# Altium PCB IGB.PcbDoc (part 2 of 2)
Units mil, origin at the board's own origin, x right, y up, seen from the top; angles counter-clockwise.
Board outline 7000 x 12000 mil, 4 copper layers (Top Layer, GND, PWR, Bottom Layer), stack 55.52 mil thick; 229 components, 204 nets, 726 pads, 127 vias.
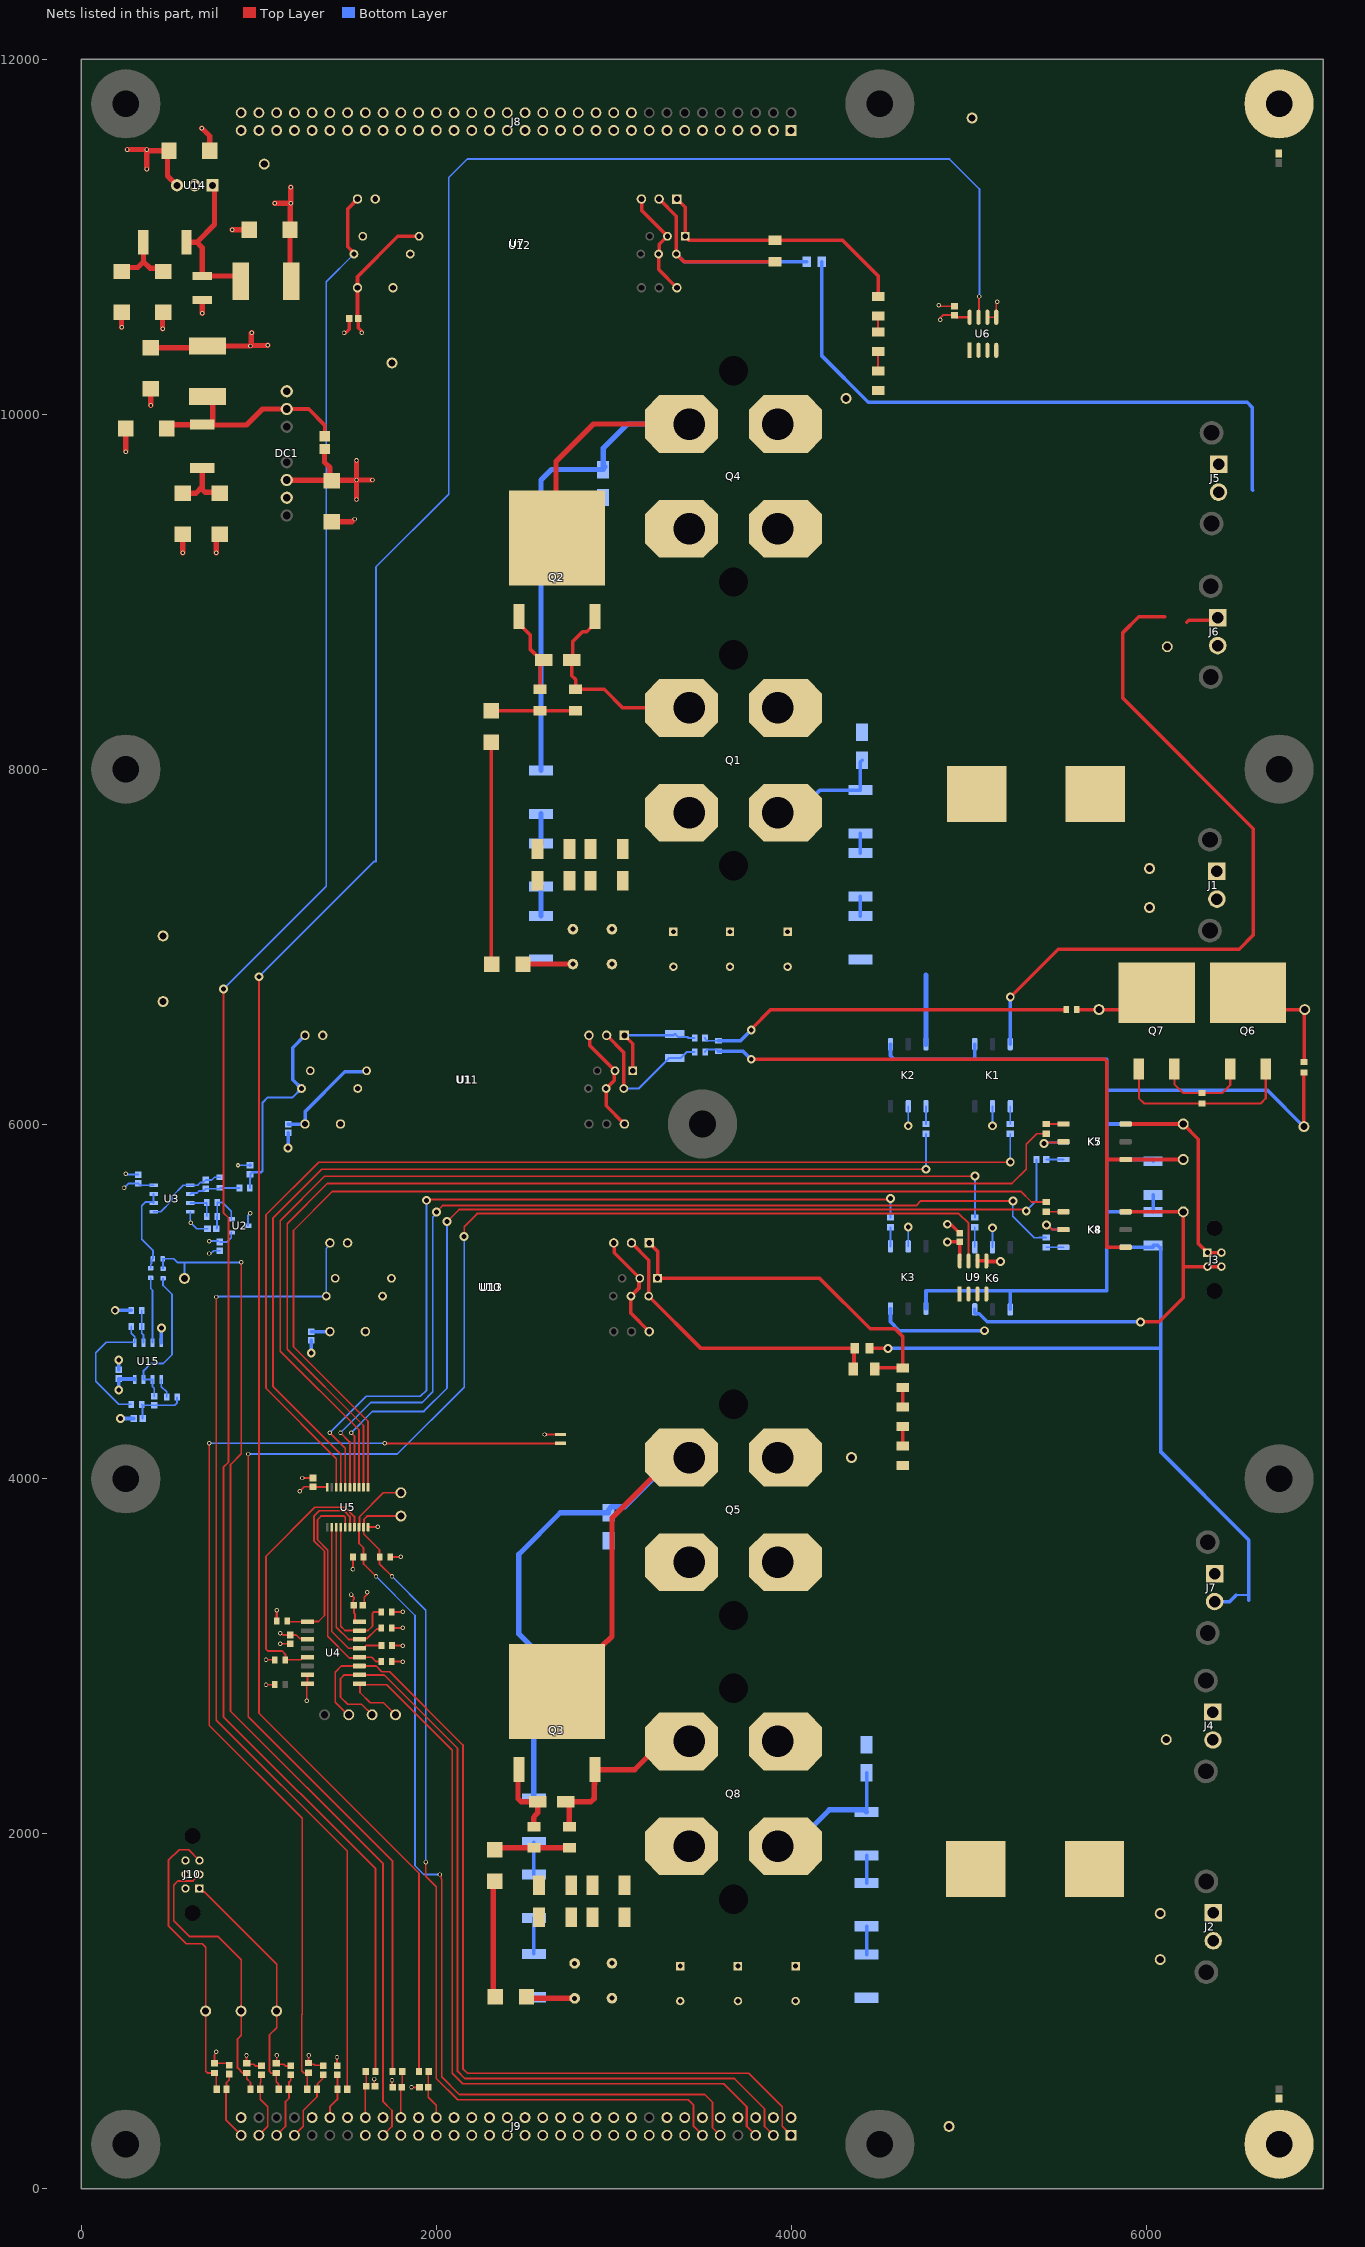
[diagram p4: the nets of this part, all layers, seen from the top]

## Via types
v1: diameter 25, hole 15, Top Layer to Bottom Layer, 92 vias
v2: diameter 50, hole 28, Top Layer to Bottom Layer, 34 vias
v3: diameter 25, hole 10, Top Layer to Bottom Layer, 1 vias

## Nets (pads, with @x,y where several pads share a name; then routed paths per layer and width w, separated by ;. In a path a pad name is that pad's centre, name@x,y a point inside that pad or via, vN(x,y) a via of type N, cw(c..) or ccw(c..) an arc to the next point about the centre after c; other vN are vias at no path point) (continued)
GND: C1.2 C2.2 C4.2 C12.1 C13.1 C14.1 C16.1 C17.1 C18.1 C19.1 C20.1 C21.1 C22.1 C23.1 C24.1 C25.1 C26.1 C27.1 C28.1 C29.1 C30.1 C31.2 C32.1 C33.2 C38.2 C39.2 C40.2 C41.2 C42.1 C43.1 C44.1 C46.1 DC1.1 DC1.7 J8.20 J8.24 J8.28 J8.32 J8.54 J8.55 J8.57 J8.59 J8.61 J8.63 J9.4 J9.8 J9.12 J9.13 J9.16 J9.17 J9.20 J9.21 J9.24 J9.25 J9.28 J9.29 J9.32 J9.33 J9.37 J9.40 J9.41 J9.44 J9.45 J9.48 J9.49 J9.52 J9.56 J36.1 J37.1 J38.1 K1.2 K2.2 K3.2 K4.2 K5.2 K6.2 K7.2 K8.2 R22.1 R23.1 R24.1 R25.1 R26.1 R27.1 R28.1 R29.1 R43.1 R45.1 R48.1 R50.1 R77.1 U1.18 U1.22 U2.3 U3.4 U4.7 U4.8 U5.10 U6.5 U6.6 U7.18 U7.22 U9.5 U9.6 U10.18 U10.22 U11.32 U11.37 U12.32 U12.37 U13.32 U13.37 U14.2 U15.4 | length 4984.8
  Top Layer w10: v1(760,770) 760,764.59 750,754.59 R45.1@750,705.84 821.61,705.84 C23.1@832.84,694.61 ; v1(930,750) 930,707.3 R48.1@931.47,705.84 937.3,700 970,700 978.93,691.07 C24.1@1014.31,691.07 ; v1(1040,2980) R27.1@1090.47,2980 ; v1(1100,750) 1100,708.68 R43.1@1097.16,705.84 1102.99,700 1140,700 1148.93,691.07 C22.1@1180,691.07 ; v1(1120,3070) 1174.84,3070 C17.1@1175.74,3070.9 ; v1@1240,4000 v1(1244.61,4004.61) C18.1@1304.95,4004.61 ; v1(1270,2750) 1270,2842.2 1272.8,2845 U4.8@1273.35,2845 U4.7@1273.35,2895 ; v1(1280,750) 1280,717.56 1270,707.56 1277.56,700 1310,700 1315.39,694.61 C26.1@1352.84,694.61 ; C30.1@1440,691.07 v1(1440,740) ; v1(1530,3490) 1530.47,3490.47 R28.1@1530.47,3560 ; C42.1@1584.61,3287.88 1593.31,3296.59 1593.31,3333.31 v1@1610,3350 ; U5.10@1615.16,3727.8 1667.8,3727.8 v1(1670,3730) ; v1(1650,616.83) 1650,581.76 C25.1@1654.61,577.16 ; R29.1@1739.53,3560 v1@1790,3560 ; R25.1@1749.06,2969.28 1749.77,2970 v1(1810,2970) ; R23.1@1749.53,3159.28 1750.25,3160 v1(1810,3160) ; R24.1@1749.53,3250 v1(1810,3250) ; v1(1750,610) 1750,575.39 C29.1@1755.39,570 ; R22.1@1750,3060 v1(1810,3060) ; v1(1860,570) C21.1@1905.39,570 ; v1(4831,10614) 4836.39,10608.61 C19.1@4921,10608.61 ; U9.5@5100,5228.06 U9.5@5103.06,5225 ; U6.6@5106,10547.06 U6.5@5156,10547.06 5156,10629 v1(5161,10634) ; v2(5425,5890) 5430,5895 5529.8,5895 K7.2@5534.8,5900 ; v2(5440,5430) 5446.57,5430 5471.57,5405 K8.2@5534.8,5405
  Top Layer w12: v1@1100,3250 1100.47,3249.53 R26.1@1100.47,3200
  Top Layer w20: v1@1490,10460 1510,10480 C20.1@1510,10540 ; v2(4880,5435) 4885.74,5429.26 4905.35,5429.26 C27.1@4950,5384.61 ; U9.6@5050,5228.06 U9.5@5100,5228.06 ; U9.5@5103.06,5225 v2(5180,5225)
  Top Layer w30: v1(226.02,10490) C40.2@226.02,10574.84 ; C2.2@249.68,9920 249.68,9790.32 v1(250,9790) ; v1(390,10050) C1.2@390,10144.84 ; v1(457.12,10482.81) 457.12,10571.96 C41.2@460,10574.84 ; v1(570,9220) C38.2@570,9324.84 ; v1(678.16,11612.39) 723.32,11567.23 C33.2@723.32,11485 ; v1(680,10570) C32.1@680,10644.17 ; v1(760,9220) 760,9304.84 C39.2@780,9324.84 ; v1(850,11040) C31.2@944.84,11040 ; C4.2@1410,9394.84 1524.84,9394.84 1530,9400
  Bottom Layer w10: v1(250,5720) 255.39,5714.61 C13.1@320,5714.61 ; v1@613.35,5446.65 U3.4@613.35,5505 ; v1(616.67,5443.33) 650,5410 C14.1@710.39,5410 ; v1(720,5270) 729.19,5270 744.58,5285.39 C16.1@780,5285.39 ; v3@882.7,5767.3 C46.1@949.3,5767.3 ; U2.3@939.24,5426 939.24,5485.24 v1(950.62,5496.62) ; K3.2@4660,5310.2 v2(4660,5420) ; v2(4660,5990) K2.2@4660,6099.8 ; K6.2@5135,5305.2 v2(5135,5415) ; v2(5135,5990) K1.2@5135,6099.8 ; v2(5425,5890) 5430,5895 5529.61,5895 K5.2@5534.61,5900 ; v2(5440,5430) 5446.57,5430 5471.57,5405 K4.2@5534.61,5405
  Bottom Layer w20: v2(190,4950) R77.1@280.47,4950 ; C43.1@210,4614.61 v2(210,4670) ; v2(220,4340) C44.1@295.39,4340 ; U15.4@450,4766.69 v2(450,4850) ; v3(882,5768) v3@882.7,5767.3 ; C46.1@949.3,5767.3 C46.1@950,5766.61 ; v2(1165,5865) C12.1@1165,5950.39 ; v2(1295,4710) C28.1@1295,4780.79
  other v1: 1100,3260 1610,3360 1800,3560 1540,9410 1480,10460
HCB_MEDIA_EN: J8.30
HPB_5V_CURRENT: J9.34
HPB_5V_VOLTAGE: J9.30
HPB_24V_CURRENT: J9.26
HPB_24V_VOLTAGE: J9.22
HPB_CISCO1_CURRENT: J9.2
HPB_CISCO1_EN: J8.49
HPB_CISCO2_CURRENT: J9.6
HPB_CISCO2_EN: J8.51
HPB_ISO24V_CURRENT: J9.14
HPB_MEDIA_CURRENT: J9.64
HPB_SYNCBOX_CURRENT: J9.10
HPB_SYNCBOX_EN: J8.53
HPB_TEMP0: J8.44
HPB_TEMP1: J8.46
HPB_TEMP2: J8.48
HPB_TEMP3: J8.50
HPB_TEMP4: J8.52
HPB_VICOR1_TEMP: J8.38
HPB_VICOR2_TEMP: J8.40
HPB_VICOR3_TEMP: J8.42
I2C_SCL: J8.26
I2C_SDA: J8.22
IGB1_CHB_RLY_EN: J8.25
INPUT+: C11.2 R17.2 U1.1 U11.1 | length 627.7
  Top Layer w20: U1.1@3060,6500 3107,6453 U11.1@3107,6300
  Bottom Layer w12: U1.1@3060,6500 3337.09,6500 C11.2@3345,6507.91 3361.64,6491.28 3415.45,6491.28 3421.72,6485 R17.2@3455.47,6485
INPUT-: U1.3 U1.38 U11.3 U11.4 | length 624.3
  Top Layer w20: U1.3@2860,6500 2863.57,6496.43 2863.57,6443.43 U11.3@3007,6300 3002.39,6295.39 3002.39,6245.39 U11.4@2957,6200 2957,6103 U1.38@3060,6000
INPUT_COMMON: C11.1 R18.2 U1.2 U11.2 | length 824
  Top Layer w20: U1.2@2960,6500 3057,6403 U11.2@3057,6200
  Bottom Layer w12: U11.2@3057,6200 3140.43,6200 3312.52,6372.09 C11.1@3345,6372.09 3377.48,6372.09 3410.39,6405 R18.2@3455.94,6405
IPB1_BOARD_TEMP: J8.34
IPB1_CHA_CURRENT_SET: J8.1
IPB1_CHA_FET_EN: J8.21
IPB1_CHA_I: J9.15
IPB1_CHA_RLY_EN: J8.17
IPB1_CHB_CURRENT_SET: J8.5
IPB1_CHB_FET_EN: J8.29
IPB1_CHB_I: J9.23
IPB1_CHC_CURRENT_SET: J8.9
IPB1_CHC_FET_EN: J8.37
IPB1_CHC_I: J9.31
IPB1_CHC_RLY_EN: J8.33
IPB1_CHD_CURRENT_SET: J8.13
IPB1_CHD_FET_EN: J8.45
IPB1_CHD_I: J9.39
IPB1_CHD_RLY_EN: J8.41
IPB1_RESET: J9.36
IPB2_BOARD_TEMP: J8.36
IPB2_CHA_CURRENT_SET: J8.3
IPB2_CHA_FET_EN: J8.23
IPB2_CHA_I: J9.19
IPB2_CHA_RLY_EN: J8.19
IPB2_CHB_CURRENT_SET: J8.7
IPB2_CHB_FET_EN: J8.31
IPB2_CHB_I: J9.27
IPB2_CHB_RLY_EN: J8.27
IPB2_CHC_CURRENT_SET: J8.11
IPB2_CHC_FET_EN: J8.39
IPB2_CHC_I: J9.35
IPB2_CHC_RLY_EN: J8.35
IPB2_CHD_CURRENT_SET: J8.15
IPB2_CHD_FET_EN: J8.47
IPB2_CHD_I: J9.43
IPB2_CHD_RLY_EN: J8.43
IPB2_RESET: J9.38
L_INPUT+: R52.2 R66.2 U10.1 U13.1 | length 2076.1
  Top Layer w20: U10.1@3200,5330 3247,5283 U13.1@3247,5130 4160,5130 4445,4845 4585,4845 4630,4800 R66.2@4630,4625.12 4475.16,4625.12 R52.2@4470.04,4620
L_INPUT-: U10.3 U10.38 U13.3 U13.4 | length 624.3
  Top Layer w20: U10.3@3000,5330 3003.57,5326.43 3003.57,5273.43 U13.3@3147,5130 3142.39,5125.39 3142.39,5075.39 U13.4@3097,5030 3097,4933 U10.38@3200,4830
L_INPUT_COMMON: R14.2 R52.1 U10.2 U13.2 | length 1742.6
  Top Layer w20: U10.2@3100,5330 3197,5233 U13.2@3197,5030 3492,4735 R14.2@4358.66,4735 4354.31,4730.65 4354.31,4624.35 R52.1@4349.96,4620
L_OUTPUT_HIGH: R54.1 U10.19 U13.38 | length 5700.9
  Top Layer w10: v1(760,5025) 760,2640 1497.56,1902.44 R54.1@1497.56,560
  Bottom Layer w10: v1(760,5025) 762.5,5027.5 1377.5,5027.5 U13.38@1380,5030 1380,5298.32 1400,5318.32 U10.19@1400,5330
N187_L_OUT: C6.2 C8.2 C10.2 C35.1 C37.1 D6.A J2.B J4.B J7.B J15.1 J19.1 K4.6 R10.2 R14.1 R33.1 R36.1 | length 4530.3
  Top Layer w20: R14.1@4441.34,4735 v2(4545,4735)
  Top Layer w30: D6.A@2508.58,1080 2516.61,1071.97 C37.1@2779.61,1071.97
  Bottom Layer w10: 6508.85,3345 6580,3345
  Bottom Layer w20: v2(4545,4735) 6084.13,4735 ; K4.6@5885.2,5305 6040,5305 R10.2@6040,5315.51 6066.57,5315.51 6084.13,5297.95 6084.13,4735 ; J7.B@6387.13,3308.26 6472.11,3308.26 6508.85,3345 ; 6580,3315 6580,3345 6580,3655 6084.13,4150.87 6084.13,4735
N187_R_OUT: C5.2 C7.2 C9.2 C34.1 C36.1 D4.A J1.B J5.B J6.B J13.1 J18.1 K2.6 R13.1 R30.1 R51.1 | length 4230.6
  Top Layer w20: J6.B@6404.13,8696.26 J6.B@6413.74,8686.65
  Top Layer w30: D4.A@2488.58,6900 2490.16,6901.57 C34.1@2770,6901.57
  Bottom Layer w20: R13.1@4171.34,10860 4171.34,10331.66 4435,10068 6570,10068 6600,10038 6600,9575 6602.48,9572.52
  Bottom Layer w30: K2.6@4760,6450.2 4760,6840
NetC2_1: C2.1 C3.1 DC1.2 L1.2 R1.2 | length 1190.9
  Top Layer w20: DC1.2@1157.18,10030 1280,10030 1370,9940 C3.1@1370,9876.42
  Top Layer w30: C2.1@480,9920 502.05,9942.05 R1.2@680,9942.05 ; DC1.2@1157.18,10030 1020,10030 930,9940 742.05,9940 740,9942.05 L1.2@740,10070 ; L1.2@740,10070 L1.2@710,10100 L1.2@740,10070
NetC5_1: C5.1 C7.1 C9.1 L2.2 Q1.D R67.1 R71.1
NetC6_1: C6.1 C8.1 C10.1 L3.2 Q8.D R68.1 R73.1
NetC14_2: C14.2 R9.1 R86.1 U2.2 | length 293.9
  Bottom Layer w10: C14.2@759.61,5410 764.53,5414.92 R9.1@764.53,5480 765.06,5480.53 R86.1@765.06,5557 795.8,5557 844.76,5508.05 U2.2@844.76,5463.4
NetC15_1: C15.1 R19.2 R20.1 U3.2 | length 292
  Bottom Layer w10: U3.2@613.35,5605 619.17,5610.83 650.83,5610.83 661.69,5621.69 686.3,5621.69 C15.1@700,5635.39 775.8,5635.39 R20.1@780.88,5640.47 781.35,5640 R19.2@890.47,5640
NetC15_2: C15.2 R20.2 U3.1 U3.5 | length 468.4
  Bottom Layer w10: U3.5@406.65,5505 446.26,5505 510,5568.74 510,5591.26 573.74,5655 U3.1@613.35,5655 655,5655 670.91,5670.91 686.3,5670.91 C15.2@700,5684.61 734.61,5684.61 750,5700 780.4,5700 R20.2@780.88,5699.53
NetC21_2: C21.2 J9.42 R41.2 | length 269.8
  Top Layer w10: C21.2@1954.61,570 1954.61,657.05 R41.2@1957.56,660 ; C21.2@1955.12,560 1955.12,514.88 2000,470 J9.42@2000,400
NetC22_2: C22.2 J9.59 R42.1 | length 377
  Top Layer w10: J9.59@1100,300 1150,350 1150,490 1170,510 1170,557.56 R42.1@1167.56,560 1170,562.44 1170,600 1180,610 C22.2@1180,641.86
NetC23_2: C23.2 J9.63 R44.1 | length 388.1
  Top Layer w10: C23.2@832.84,645.39 832.84,612.84 817.56,597.56 R44.1@817.56,560 814.84,557.28 814.84,385.16 J9.63@900,300
NetC24_2: C24.2 J9.61 R46.1 | length 382.9
  Top Layer w10: J9.61@1000,300 1050,350 1050,460 1007.56,502.44 R46.1@1007.56,560 1007.56,597.56 1010,600 1010,637.55 C24.2@1014.31,641.86
NetC25_2: C25.2 J9.50 R47.2 | length 244.1
  Top Layer w10: J9.50@1600,400 C25.2@1600,560 ; R47.2@1602.44,660 1605.39,657.05 C25.2@1605.39,577.16
NetC26_2: C26.2 J9.57 R49.1 | length 403.5
  Top Layer w10: J9.57@1200,300 1250,350 1250,440 1327.56,517.56 R49.1@1327.56,560 1330,562.44 1330,590 1360,620 C26.2@1360,637.19
NetC29_2: C29.2 J9.46 R53.2 | length 253.6
  Top Layer w10: J9.46@1800,400 1800,554.34 C29.2@1805.66,560 ; C29.2@1804.61,570 1807.56,572.95 R53.2@1807.56,660
NetC30_2: C30.2 J9.54 R54.2 | length 260.5
  Top Layer w10: J9.54@1400,400 1400,460 1442.44,502.44 R54.2@1442.44,560 1442.44,639.42 C30.2@1440,641.86
NetC32_2: C32.2 L4.2 R2.2 U14.1 | length 857.8
  Top Layer w30: R2.2@592.05,10970 650,10970 ; U14.1@738,11291 750,11279 750,11070 650,10970 ; L4.2@897.5,10749.73 867.23,10780 C32.2@680,10780 680,10940 650,10970
NetC34_2: C34.2 C36.2 R72.2 R75.2
NetC35_2: C35.2 C37.2 R74.2 R76.2
NetC38_1: C38.1 C39.1 R1.1 | length 354.1
  Top Layer w30: C38.1@570,9555.16 645.16,9555.16 680,9590 ; R1.1@680,9697.95 680,9590 ; C39.1@780,9555.16 775.16,9560 697.57,9560 680,9577.57 680,9590
NetC40_1: C40.1 C41.1 R2.1 | length 390.3
  Top Layer w30: C40.1@226.02,10805.16 248.15,10827.28 317.28,10827.28 350,10860 ; R2.1@347.95,10970 350,10967.95 350,10860 ; C41.1@460,10805.16 441.47,10823.69 386.31,10823.69 350,10860
NetC44_2: C44.2 C45.1 R79.2 R80.1 | length 313.6
  Bottom Layer w10: R79.2@339.53,4420 R79.2@344.13,4415.39 ; C44.2@344.61,4340 344.61,4414.92 R79.2@344.13,4415.39 ; R80.1@539.06,4460 539.06,4429.06 525.39,4415.39 C45.1@410,4415.39 R79.2@344.13,4415.39
NetC45_2: C45.2 R83.1 U15.6 U15.7 | length 847.5
  Bottom Layer w10: C45.2@410,4464.61 410,4510 400,4520 U15.6@400,4560 U15.7@350,4560 350,4610 390,4650 460,4650 510,4700 510,5040 460,5090 R83.1@460,5130
NetD1_1: D1.1 D7.1 D10.1 Q1.S1 Q1.S2 Q2.S Q4.S1 Q4.S2 R3.2 | length 1171.5
  Top Layer w20: Q2.S@2894.57,8861.1 2894.57,8820.75 2847.87,8774.06 2824.05,8774.06 2770,8720 2770,8621.26 D7.1@2763.74,8615 2763.74,8526.26 2785,8505 R3.2@2785,8450.04 2945.69,8450.04 3050.73,8345 Q1.S2@3425,8345
NetD1_2: D1.2 Q1.G R7.2 | length 689.7
  Bottom Layer w20: Q1.G@3925,7755 4035,7755 4160,7880 4387.95,7880 R7.2@4390,7882.05 4390,8040 D1.2@4400,8050
NetD2_1: D2.1 D8.1 D9.1 Q3.S Q5.S1 Q5.S2 Q8.S1 Q8.S2 R4.2 | length 1075.5
  Top Layer w30: D8.1@2728.74,2180 D8.1@2731.54,2180 ; R4.2@2750,2040.08 2750,2161.54 D8.1@2731.54,2180 ; 2889.57,2281.1 2889.57,2197.57 2871.99,2180 D8.1@2731.54,2180 ; 2894.57,2281.1 Q3.S@2894.57,2361.1 3118.57,2361.1 3277.46,2520 Q8.S2@3425,2520
NetD2_2: D2.2 Q8.G R31.2 | length 810.8
  Bottom Layer w20: R31.2@4425,2122.05 D2.2@4425,2342.52
  Bottom Layer w30: Q8.G@3925,1930 4010,1930 4215,2135 4412.05,2135 R31.2@4425,2122.05
NetD3_A: D3.A D4.C | length 1252
  Top Layer w20: D3.A@2310,8151.42 2310,6901.42 D4.C@2311.42,6900
NetD3_C: D3.C R3.1 R6.1 | length 483.2
  Top Layer w20: D3.C@2310,8328.58 2311.38,8329.96 2583.62,8329.96 R6.1@2585,8328.58 ; R6.1@2585,8329.96 R6.1@2605,8329.96 ; R6.1@2600,8324.96 R6.1@2605,8329.96 ; R3.1@2785,8329.96 R6.1@2605,8329.96
NetD5_A: D5.A D6.C | length 660.3
  Top Layer w30: D5.A@2330,1731.42 2320,1721.42 2320,1091.42 D6.C@2331.42,1080
NetD5_C: D5.C R4.1 R5.1 | length 424.7
  Top Layer w30: D5.C@2330,1908.58 2341.42,1920 R4.1@2750,1920
NetD7_2: D7.2 Q2.G R6.2 | length 478.6
  Top Layer w20: Q2.G@2465.43,8861.1 2465.43,8820.75 2528.3,8757.88 2528.3,8677.21 2590.51,8615 D7.2@2606.26,8615 ; R6.2@2585,8450.04 D7.2@2585,8615
NetD8_2: D8.2 Q3.G R5.2 | length 422.4
  Top Layer w30: Q3.G@2465.43,2361.1 2460.43,2356.1 2460.43,2197.57 2478.01,2180 D8.2@2571.26,2180 2571.26,2117.57 2553.69,2100 ; R5.2@2550,2040.08 2550,2091.54
NetD9_2: D9.2 Q3.D Q5.G R34.2 | length 4291.5
  Top Layer w30: Q3.D@2680,2802.05 2681.97,2802.05 2934.69,3054.76 2934.69,3056.73 2990,3112.05 2990,3780 3330,4120 Q5.G@3425,4120
  Bottom Layer w30: R34.2@2550,2197.05 2550,3040 2465,3125 2465,3575 2698.74,3808.74 D9.2@2970,3808.74 2970,3824.49 2988.46,3842.95 3062.95,3842.95 3340,4120 Q5.G@3425,4120
NetD10_2: D10.2 Q2.D Q4.G R37.2 | length 3949.4
  Top Layer w30: Q2.D@2680,9302.05 2675,9307.05 2675,9735 2885,9945 Q4.G@3425,9945
  Bottom Layer w30: R37.2@2590,7992.05 2590,9630 2648.74,9688.74 D10.2@2940,9688.74 D10.2@2940,9704.49 ; D10.2@2950,9704.49 2940,9714.49 2940,9807.93 3077.07,9945 Q4.G@3425,9945
NetFB1_2: FB1.2 MH3.1
NetFB2_2: FB2.2 MH6.1
NetJ1_A: J1.A J16.1 L2.1
NetJ2_A: J2.A J14.1 L3.1
NetJ3_1: J3.1 J3.3 J30.1 K7.6 | length 1185
  Top Layer w20: K7.6@5885.2,6000 J30.1@6210,6000 6295,5915 6295,5326.26 J3.1@6346.26,5275 J3.3@6425,5275
NetJ3_2: J3.2 J3.4 J31.1 K6.6 K8.6 | length 2296.4
  Top Layer w20: K8.6@5885.2,5505 J31.1@6210,5505 6210,5196.26 ; v2(5970,4885) 6075,4885 6210,5020 6210,5196.26 ; J3.4@6425,5196.26 J3.2@6346.26,5196.26 6210,5196.26
  Bottom Layer w20: K6.6@5035,4954.8 5035,4934.8 5040,4929.8 5060,4929.8 5104.8,4885 v2(5970,4885)
NetJ9_1: J9.1 J24.1 U4.11 | length 5088.9
  Top Layer w10: J24.1@1506.67,2670 1500,2670 1430,2740 1430,2910 1465,2945 U4.11@1566.65,2945 1660.46,2945 1692.46,2913 1737.02,2913 2150,2500.02 2150,675.55 2175.55,650 3760,650 3950,460 3950,350 J9.1@4000,300
NetJ9_3: J9.3 J25.1 U4.10 | length 4972.1
  Top Layer w10: J25.1@1638.34,2670 1578.34,2730 1500,2730 1460,2770 1460,2874.14 1480.86,2895 U4.10@1566.65,2895 1705,2895 2120,2480 2120,660 2160,620 3680,620 3850,450 3850,350 J9.3@3900,300
NetJ9_5: J9.5 J26.1 U4.9 | length 4716
  Top Layer w10: U4.9@1566.65,2845 U4.9@1570,2841.65 ; J26.1@1770,2670 1702.11,2737.89 1627.97,2737.89 1570,2795.86 U4.9@1570,2841.65 ; 3620,590 2150,590 2090,650 2090,2470 1720,2840 1571.65,2840 U4.9@1570,2841.65
  Top Layer w12: 3620,590 3750,460 3750,350 J9.5@3800,300
NetJ9_9: J9.9 J28.1 R28.2 U5.8 | length 5483.6
  Top Layer w10: v1(1660,3450) 1589.53,3520.47 R28.2@1589.53,3560 1590,3560.47 1590,3610 1563.98,3636.02 U5.8@1563.98,3727.8 1566.85,3730.67 1566.85,3786.85 1701.66,3921.66 J28.1@1800,3921.66 ; v1(2020,1770) 2027.65,1762.35 2027.65,1746.49 2030,1744.14 2030,630 2130,530 3512.98,530 3556.49,486.49 3556.49,343.51 J9.9@3600,300
  Bottom Layer w10: v1(1660,3450) 1880,3230 1880,1820 1930,1770 v1(2020,1770)
NetJ9_11: J9.11 J29.1 R29.2 U5.9 | length 5241.6
  Top Layer w10: v1(1750,3450) 1680.47,3519.53 R29.2@1680.47,3560 1680,3560.47 1680,3600 1590.83,3689.17 1590.83,3726.54 U5.9@1589.57,3727.8 1592.44,3730.67 1592.44,3772.44 1610,3790 J29.1@1800,3790 ; v1(1940,1840) 1940,1760 2000,1700 2000,620 2120,500 3420,500 3450,470 3450,350 J9.11@3500,300
  Bottom Layer w10: v1(1750,3450) 1940.29,3259.71 1940.29,1840.29 v1(1940,1840)
NetJ9_47: J9.47 J23.1 R82.2 R83.2 | length 5939.1
  Top Layer w10: v1(900,5220) 900,4140.29 840,4080.29 840,2690 1700,1830 1700,490 1750,440 1750,350 J9.47@1700,300
  Bottom Layer w10: R83.2@460,5185.12 458.78,5186.34 458.78,5238.78 R82.2@457.56,5240 520,5240 540,5220 580,5220 ; J23.1@580,5130 580,5220 ; v1(900,5220) 580,5220
NetJ10_1: J10.1 J32.1 R42.2 R43.2 | length 1372.1
  Top Layer w10: J10.1@664.72,1691.26 683.35,1672.64 692.36,1672.64 1100,1265 J32.1@1100,1000 1100,906.1 1060,866.1 1060,660 1070,650 1096.44,650 R43.2@1097.16,650.72 1097.16,602.84 1110,590 1110,562.44 R42.2@1112.44,560
NetJ10_2: J10.2 J34.1 R46.2 R48.2 | length 1622.6
  Top Layer w10: J10.2@664.72,1770 628.1,1733.38 543.38,1733.38 520,1710 520,1510 610,1420 770,1420 900,1290 900,862.76 880,842.76 880,680 910,650 930.75,650 R48.2@931.47,650.72 931.47,618.53 952.44,597.56 R46.2@952.44,560
NetJ10_3: J10.3 J33.1 R44.2 R45.2 | length 1703.5
  Top Layer w10: J10.3@664.72,1848.74 603.46,1910 550,1910 490,1850 490,1480 590,1380 680,1380 700,1360 J33.1@700,1000 700,661.44 710.72,650.72 R45.2@750,650.72 760,640.72 760,562.44 R44.2@762.44,560
NetJ17_1: J17.1 Q4.D R61.1 U6.1 U6.2
NetJ20_1: J20.1 Q5.D R64.1 U9.1 U9.2
NetJ21_1: J21.1 K1.4 K2.4 K3.4 K4.4 K5.4 K6.4 R84.1 | length 5622.8
  Top Layer w20: J21.1@6890,5985 R84.1@6890,6290.47
  Bottom Layer w20: K2.4@4560,6450.2 4560,6385 4580,6365 5035,6365 ; K3.4@4760,4959.8 4760,5060 5235,5060 ; K1.4@5035,6450.2 5035,6365 ; K6.4@5235,4954.8 5235,5060 ; K4.4@5885.2,5505 5785.9,5505 5780,5510.9 ; K5.4@5885.2,6000 5780,6000 ; J21.1@6890,5985 6683.73,6191.27 5780,6191.27 ; 5035,6365 5780,6365 5780,6191.27 ; 5235,5060 5780,5060 5780,5510.9 ; 5780,5510.9 5780,6000 ; 5780,6000 5780,6191.27
NetJ22_1: J22.1 K7.4 K8.4 R16.1 R18.1 | length 3884.6
  Top Layer w20: v2(3775,6365) 5768.28,6365 5780,6353.28 5780,5800 ; K8.4@5885.2,5305 5780,5305 5780,5800 ; J22.1@6210,5800 K7.4@5885.2,5800 5780,5800
  Bottom Layer w10: R18.1@3515,6405 3515,6408.94 3525.75,6419.69 3531.29,6419.69 3531.61,6420 3580.47,6420 R16.1@3590,6410.47
  Bottom Layer w20: R16.1@3590,6410.47 3728.55,6410.47 3774.02,6365 v2(3775,6365)
NetJ39_1: J39.1 Q6.D R84.2 | length 656.9
  Top Layer w20: Q6.D@6575,6740 6670,6645 J39.1@6895,6645 6892.5,6642.5 6892.5,6352.03 R84.2@6890,6349.53
NetJ40_1: J40.1 Q7.D R85.1 | length 489.8
  Top Layer w20: R85.1@5609.53,6645 J40.1@5735,6645 5965,6645 Q7.D@6060,6740
NetK1_1: K1.1 R55.2 | length 99.8
  Bottom Layer w10: R55.2@5235,6000 K1.1@5235,6099.8
NetK2_1: K2.1 R56.2 | length 99.8
  Bottom Layer w10: R56.2@4760,6000 K2.1@4760,6099.8
NetK3_1: K3.1 R57.2 | length 107.2
  Bottom Layer w10: K3.1@4560,5310.2 R57.2@4560,5417.44
NetK4_1: K4.1 R58.2 | length 97.2
  Bottom Layer w10: R58.2@5437.56,5305 K4.1@5534.8,5305
NetK5_1: K5.1 R59.2 | length 97.2
  Bottom Layer w10: R59.2@5437.56,5800 K5.1@5534.8,5800
NetK5_6: K5.6 R38.1 | length 165.3
  Bottom Layer w20: K5.6@5885.2,5800 6040,5800 R38.1@6040,5789.49
NetK6_1: K6.1 R60.2 | length 112.2
  Bottom Layer w10: K6.1@5035,5305.2 R60.2@5035,5417.44
NetK7_1: K7.1 R69.2 | length 97.2
  Top Layer w10: R69.2@5437.56,6000 K7.1@5534.8,6000
NetK8_1: K8.1 R70.2 | length 97.2
  Top Layer w10: R70.2@5437.56,5505 K8.1@5534.8,5505
NetQ6_G: Q6.G Q7.S R15.2 | length 529.7
  Top Layer w12: Q7.S@6160,6310 6160,6225 6210.47,6174.53 R15.2@6315,6174.53 6429.53,6174.53 6475,6220 Q6.G@6475,6310
NetQ6_S: Q6.S Q7.G R15.1 | length 1069.9
  Top Layer w12: Q7.G@5960,6310 5960,6145 5989.53,6115.47 R15.1@6315,6115.47 6315.47,6115 6645,6115 6675,6145 Q6.S@6675,6310
NetR7_1: R7.1 R8.2 | length 111.4
  Bottom Layer w20: R8.2@4390,7526.55 R7.1@4390,7637.95
NetR8_1: R8.1 R30.2 | length 110.4
  Bottom Layer w20: R30.2@4390,7172.05 R8.1@4390,7282.45
NetR9_2: R9.2 R86.2 U3.3 | length 170.7
  Bottom Layer w10: U3.3@613.35,5555 704,5555 R86.2@706,5557 706,5480.53 R9.2@705.47,5480
NetR10_1: R10.1 R38.2 | length 96
  Bottom Layer w20: R10.1@6040,5504.49 R38.2@6040,5600.51
NetR16_2: R16.2 R17.1 R85.2 | length 2120.3
  Top Layer w20: v2(3775,6530) 3775,6535 3885,6645 R85.2@5550.47,6645
  Bottom Layer w10: R17.1@3514.53,6485 3514.53,6481.06 3525.28,6470.31 3529.21,6470.31 3530,6469.53 R16.2@3590,6469.53
  Bottom Layer w20: R16.2@3590,6469.53 3714.53,6469.53 v2(3775,6530)
NetR22_2: R22.2 U4.13 U5.2 | length 914.8
  Top Layer w10: U5.2@1410.43,3727.8 1410.43,3139.57 1505,3045 U4.13@1566.65,3045 1590.28,3045 1597.07,3051.8 1597.07,3052.97 1604.1,3060 R22.2@1690.94,3060
NetR23_2: R23.2 U4.14 U5.3 | length 873.5
  Top Layer w10: U5.3@1436.02,3727.8 1436.02,3163.98 1505,3095 U4.14@1566.65,3095 1572.25,3100.6 1610.6,3100.6 1663.75,3153.75 1684.95,3153.75 R23.2@1690.47,3159.28
NetR24_2: R24.2 U4.15 U5.4 | length 884.2
  Top Layer w10: U5.4@1461.61,3727.8 1461.61,3168.39 1485,3145 U4.15@1566.65,3145 1615,3145 1640,3170 1640,3242.97 1647.03,3250 R24.2@1690.47,3250
NetR25_2: R25.2 U4.12 U5.5 | length 1270.8
  Top Layer w10: U5.5@1487.2,3727.8 1487.2,3782.8 1480,3790 1350,3790 1330,3770 1330,3656.26 1388,3598.26 1388,3112 1510,2990 1561.65,2990 U4.12@1566.65,2995 1635,2995 1660,2970 1689.28,2970 R25.2@1690,2969.28
NetR26_2: R26.2 U4.1 U5.6 | length 1100.1
  Top Layer w10: R26.2@1159.53,3200 1164.53,3195 U4.1@1273.35,3195 1274.2,3195.86 1335.86,3195.86 1370,3230 1370,3590.8 1310,3650.8 1310,3790 1340,3820 1480,3820 1512.8,3787.2 U5.6@1512.8,3727.8
NetR27_2: R27.2 U4.5 U5.7 | length 1501
  Top Layer w10: U4.5@1273.35,2995 1249.72,2995 1241.93,2987.2 1241.93,2985.86 1236.07,2980 R27.2@1149.53,2980 1149.53,3010.47 1130,3030 1050,3030 1040,3040 1040,3564.14 1315.86,3840 1485.46,3840 1538.39,3787.07 U5.7@1538.39,3727.8
NetR31_1: R31.1 R32.2 | length 155.9
  Bottom Layer w20: R32.2@4425,1722.05 R31.1@4425,1877.95
NetR32_1: R32.1 R33.2 | length 158.9
  Bottom Layer w20: R33.2@4425,1319.09 R32.1@4425,1477.95
NetR34_1: R34.1 R35.2 | length 183.9
  Bottom Layer w20: R35.2@2550,1769.09 R34.1@2550,1952.95
NetR35_1: R35.1 R36.2 | length 203
  Bottom Layer w20: R36.2@2550,1322.05 R35.1@2550,1525
NetR37_1: R37.1 R39.2 | length 165.9
  Bottom Layer w30: R39.2@2590,7582.05 R37.1@2590,7747.95
NetR39_1: R39.1 R51.2 | length 165.9
  Bottom Layer w30: R51.2@2590,7172.05 R39.1@2590,7337.95
NetR41_1: R41.1 U6.7 | length 15327
  Top Layer w10: v2(1000,6830) 1000,2680 1902.44,1777.56 R41.1@1902.44,660
  Top Layer w12: U6.7@5056,10547.06 5058.09,10549.14 5058.09,10661.09 v1(5061,10664)
  Bottom Layer w10: v2(1000,6830) 1650,7480 1660,7480 1660,9140 2070,9550 2070,11335 2174,11439 4892,11439 5061,11270 v1(5061,10664)
NetR49_2: R49.2 R50.2 U8.2 | length 5870.8
  Top Layer w10: v1(720,4200) 720,2610 1243.91,2086.09 1243.91,981.81 1242,979.91 1242,663.86 1255.86,650 R50.2@1277.56,650 ; R49.2@1272.44,560 1272.44,644.88 R50.2@1277.56,650 ; R50.2@1280,652.44 R50.2@1277.56,650
  Top Layer w12: v1(1710,4200) 1820,4200 U8.2@2700,4200
  Bottom Layer w10: v1(720,4200) v1(1710,4200)
NetR53_1: R53.1 U9.7 | length 9202.6
  Top Layer w10: v1(940,4140) 940,2660 1752.44,1847.56 R53.1@1752.44,660 ; v2(2156.84,5365.68) 2156.84,5421.84 2230,5495 4945,5495 5000,5440 U9.7@5000,5228.06
  Bottom Layer w10: v1(940,4140) 1780,4140 2156.84,4516.84 v2(2156.84,5365.68)
NetR55_1: R55.1 U5.18 | length 6177.8
  Top Layer w10: U5.18@1436.02,3952.2 1436.02,4113.98 1040,4510 1040,5488.14 1336.86,5785 v2(5235,5785)
  Bottom Layer w10: v2(5235,5785) R55.1@5235,5944.88
NetR56_1: R56.1 U5.17 | length 5670.6
  Top Layer w10: U5.17@1461.61,3952.2 1461.61,4138.39 1080,4520 1080,5471.57 1353.43,5745 v2(4760,5745)
  Bottom Layer w10: v2(4760,5745) R56.1@4760,5944.88
NetR57_1: R57.1 U5.16 | length 4784.9
  Top Layer w10: v1(1400,4260) 1487.2,4172.8 U5.16@1487.2,3952.2 ; v2(1945,5570) 1950,5575 4555,5575 v2(4560,5580)
  Bottom Layer w10: v1(1400,4260) 1605,4465 1910,4465 1945,4500 v2(1945,5570) ; R57.1@4560,5472.56 v2(4560,5580)
NetR58_1: R58.1 U5.15 | length 5567.9
  Top Layer w10: v1(1460,4260) 1512.8,4207.2 U5.15@1512.8,3952.2 ; v2(2000,5505) 2035,5540 4705,5540 4731.51,5566.51 v2(5249.52,5566.51)
  Bottom Layer w10: v1(1460,4260) 1630,4430 1920,4430 1980,4490 1980,5474.18 2000,5494.18 v2(2000,5505) ; v2(5249.52,5566.51) 5249.52,5480.48 5370.86,5359.14 5395.89,5359.14 5396.86,5360.12 R58.1@5437.56,5360.12
NetR59_1: R59.1 U5.14 | length 5509
  Top Layer w10: v1(1520,4260) 1538.39,4241.61 U5.14@1538.39,3952.2 ; v2(2060,5450) 2127.65,5517.65 5317.35,5517.65 v2(5325,5510)
  Bottom Layer w10: v1(1520,4260) 1640,4380 1930,4380 2060,4510 v2(2060,5450) ; v2(5325,5510) 5382.44,5567.44 R59.1@5382.44,5800
NetR60_1: R60.1 U5.13 | length 5940.4
  Top Layer w10: U5.13@1563.98,3952.2 1563.98,4276.02 1120,4720 1120,5455 1370,5705 5035.43,5705 v2(5035.43,5705.91)
  Bottom Layer w10: R60.1@5035,5472.56 5035.43,5472.56 v2(5035.43,5705.91)
NetR61_2: R61.2 R62.1 | length 109.8
  Top Layer w10: R61.2@4490,10245.12 R62.1@4490,10354.88
NetR62_2: R62.2 R63.1 | length 89.8
  Top Layer w10: R62.2@4490,10465.12 R63.1@4490,10554.88
NetR64_2: R64.2 R65.1 | length 109.8
  Top Layer w20: R64.2@4630,4185.12 R65.1@4630,4294.88
NetR65_2: R65.2 R66.1 | length 109.8
  Top Layer w20: R65.2@4630,4405.12 R66.1@4630,4514.88
NetR67_2: R67.2 R75.1
NetR68_2: R68.2 R76.1
NetR69_1: R69.1 U5.12 | length 6233.6
  Top Layer w10: U5.12@1589.57,3952.2 1589.57,4300.43 1160,4730 1160,5438.43 1386.57,5665 5245,5665 5325,5745 5325,5885 5385,5945 5437.44,5945 R69.1@5437.56,5944.88
NetR70_1: R70.1 U5.11 | length 5980.3
  Top Layer w10: U5.11@1615.16,3952.2 1615.16,4324.84 1195,4745 1195,5400 1415,5620 5295,5620 5354.88,5560.12 R70.1@5437.56,5560.12
NetR71_2: R71.2 R72.1
NetR73_2: R73.2 R74.1
NetR77_2: R77.2 R78.1 U15.2 | length 188
  Bottom Layer w10: R77.2@339.53,4950 339.53,4860.47 R78.1@339.06,4860 339.06,4820.94 350,4810 U15.2@350,4766.69
NetR78_2: R78.2 R79.1 U15.1 | length 762.1
  Bottom Layer w10: R78.2@280,4860 280,4820 300,4800 U15.1@300,4766.69 296.69,4770 140,4770 80,4710 80,4550 210,4420 R79.1@280.47,4420
NetR80_2: R80.2 U15.5 | length 112.4
  Bottom Layer w10: U15.5@450,4560 450,4520 480,4490 R80.2@480,4460
NetR81_1: R81.1 U15.3 | length 369.9
  Bottom Layer w10: R81.1@390,5132.44 390,5072.95 400,5062.95 U15.3@400,4766.69
NetR81_2: R81.2 R82.1 U3.6 U3.7 | length 510.5
  Bottom Layer w10: R81.2@390,5187.56 390,5210 394.44,5214.44 394.44,5232 R82.1@402.44,5240 402.44,5287.56 340,5350 340,5540 360,5560 401.65,5560 U3.6@406.65,5555 U3.7@406.65,5605
OUTPUT_HIGH: C46.2 R19.1 U1.19 U11.38 | length 1141.5
  Bottom Layer w10: R19.1@949.53,5640 949.53,5692.53 953,5696 C46.2@953,5714.39
  Bottom Layer w12: C46.2@953,5714.39 953,5718.27 962.7,5727.97 1012.97,5727.97 1020,5735 1020,6120 1050,6150 1190,6150 U11.38@1240,6200
  Bottom Layer w20: U11.38@1240,6200 1190,6250 1190,6430 U1.19@1260,6500
P187_L_OUT: J4.A J7.A K3.6 U9.3 U9.4 | length 625.5
  Bottom Layer w20: K3.6@4560,4959.8 4560,4885 4610,4835 v2(5090,4835)
P187_R_OUT: J5.A J6.A K1.6 U6.3 U6.4 | length 4246.2
  Top Layer w20: v2(5235,6715) 5505,6985 6525,6985 6605,7065 6605,7665 5870,8400 5870,8770 5960,8860 6105,8860 ; 6230,8828.28 6241.72,8840 6390.39,8840 J6.A@6404.13,8853.74
  Bottom Layer w20: K1.6@5235,6450.2 v2(5235,6715)
R_INPUT+: R40.2 R63.2 U7.1 U12.1 | length 1524.1
  Top Layer w20: U7.1@3355.76,11213.41 3402.76,11166.41 U12.1@3402.76,11003.41 3426.13,10980.04 R40.2@3910,10980.04 4289.96,10980.04 4490,10780 R63.2@4490,10665.12
R_INPUT-: U7.3 U7.38 U12.3 U12.4 | length 624.3
  Top Layer w20: U7.3@3155.76,11213.41 3157.24,11211.93 3157.24,11148.93 U12.3@3302.76,11003.41 3257.36,10958.02 3257.36,10908.02 U12.4@3252.76,10903.41 3252.76,10816.41 U7.38@3355.76,10713.41
R_INPUT_COMMON: R13.2 R40.1 U7.2 U12.2 | length 1679.3
  Top Layer w20: U7.2@3255.76,11213.41 3352.76,11116.41 U12.2@3352.76,10903.41 3396.21,10859.96 R40.1@3910,10859.96
  Bottom Layer w20: U12.2@3352.76,10903.41 3396.17,10860 R13.2@4088.66,10860
R_OUTPUT_HIGH: R47.1 U7.19 U12.38 | length 11275.5
  Top Layer w10: v2(800,6760) 800,5499.58 829.23,5470.35 829.23,4094.97 800,4065.74 800,2660 1657.56,1802.44 R47.1@1657.56,660
  Top Layer w20: U12.38@1535.76,10903.41 1535.76,10909.12 1500,10944.88 1500,11157.65 U7.19@1555.76,11213.41
  Bottom Layer w10: v2(800,6760) 1380,7340 1380,10720 1380,10747.65 U12.38@1535.76,10903.41
SYS_5V: C13.2 C16.2 C17.2 C18.2 C19.2 C27.2 C33.1 C42.2 J10.4 J10.5 J10.6 J35.1 R21.1 U2.1 U3.8 U4.3 U4.16 U5.20 U6.8 U8.1 U9.8 U14.3 | length 1909.7
  Top Layer w10: v1(1040,2840) R21.1@1090.47,2840 ; v1(1120,3130) 1124.06,3130 1134.06,3120 1175.63,3120 C17.2@1175.74,3120.11 1175.85,3120 1210,3120 1230,3100 1268.35,3100 U4.3@1273.35,3095 ; v1(1230,3930) 1255.39,3955.39 C18.2@1304.95,3955.39 1306.54,3953.8 U5.20@1383.25,3953.8 ; v1(1520,3347.88) 1535.39,3332.49 1535.39,3321.98 1531.3,3317.88 C42.2@1531.3,3283.79 ; C42.2@1535.39,3287.88 1535.39,3244.61 1542.16,3237.84 1542.16,3197.8 1544.95,3195 U4.16@1566.65,3195 1567.2,3195 U4.16@1570,3197.8 ; v2(4880,5335) v2@4880.39,5335.39
  Top Layer w12: v1(2610,4250) U8.1@2700,4250 ; v1@4841,10544 4856.39,10559.39 C19.2@4921,10559.39 4933.34,10547.06 U6.8@5006,10547.06
  Top Layer w20: v2@4880.39,5335.39 C27.2@4950,5335.39 U9.8@4950,5228.06
  Top Layer w30: v1(258.16,11492.39) v1(368.16,11492.39) v1(368.16,11382.39) ; v1@370.77,11485 C33.1@464,11485 ; C33.1@493,11485 C33.1@464,11485 ; U14.3@538,11291 485.19,11343.81 485.19,11463.81 C33.1@464,11485
  Bottom Layer w10: 250,5650 265.39,5665.39 C13.2@320,5665.39 330.39,5655 U3.8@406.65,5655 ; v1(720,5340) C16.2@769.39,5340 ; C16.2@780,5334.61 819.61,5334.61 844.76,5359.76 U2.1@844.76,5388.6
  other v1: 240,5640 4841,10534
SYS_15V: C3.2 C4.1 C12.2 C20.2 C28.2 C43.2 DC1.6 J12.1 U1.20 U7.20 U10.20 U11.31 U12.31 U13.31 U15.8 | length 2537
  Top Layer w20: C20.2@1559.21,10540 1559.21,10488.91 1580,10468.12 v1(1580,10460) ; C20.2@1560,10540 1555.76,10544.24 U7.20@1555.76,10713.41 1555.76,10775.76 1783.41,11003.41 U12.31@1902.76,11003.41
  Top Layer w30: DC1.6@1157.18,9630 1159.61,9627.58 C4.1@1407.58,9627.58 ; C3.2@1370,9803.58 1370,9730 1400,9700 1400,9635.16 C4.1@1407.58,9627.58 ; v1(1550,9520) v1(1550,9630) ; v1(1550,9740) v1(1550,9630) ; v1(1640,9630) v1(1550,9630) ; C4.1@1407.58,9627.58 C4.1@1410,9625.16 1412.42,9627.58 1547.58,9627.58 v1(1550,9630)
  Bottom Layer w20: v2(210,4500) C43.2@210,4565.39 212.7,4562.7 299.17,4562.7 300,4561.87 U15.8@300,4560 ; C12.2@1165,5999.61 1165.2,5999.8 1259.8,5999.8 U1.20@1260,6000 1260,6070 1484.41,6294.41 1601.41,6294.41 U11.31@1607,6300 ; C28.2@1295,4830 U10.20@1400,4830
SYS_24V: C1.1 C31.1 J8.56 J8.58 J8.60 J8.62 J8.64 J11.1 L1.1 L4.1 | length 1369.6
  Top Layer w30: C1.1@390,10375.16 700.16,10375.16 L1.1@710,10385 v1(952.43,10385) ; v1(960,10460) 956.21,10456.21 956.21,10394.24 952.43,10390.45 v1(952.43,10385) ; v1(1050,10390) 1047.5,10387.5 954.93,10387.5 v1(952.43,10385) ; v1(1090,11190) v1(1180,11190) ; v1(1180,11280) v1(1180,11190) ; L4.1@1182.5,10749.73 1175.16,10757.08 C31.1@1175.16,11040 1177.58,11042.42 1177.58,11187.58 v1(1180,11190)
pads on no net: DC1.3 DC1.5 DC1.8 J1.MT1 J1.MT2 J2.MT1 J2.MT2 J3.MT1 J3.MT2 J4.MT1 J4.MT2 J5.MT1 J5.MT2 J6.MT1 J6.MT2 J7.MT1 J7.MT2 J10.MT1 J10.MT2 K1.3 K1.5 K2.3 K2.5 K3.3 K3.5 K4.3 K4.5 K5.3 K5.5 K6.3 K6.5 K7.3 K7.5 K8.3 K8.5 MH1.1 MH2.1 MH4.1 MH5.1 MH7.1 MH8.1 MH9.1 MH10.1 MH11.1 Q1.MNT1 Q1.MNT2 Q4.MNT1 Q4.MNT2 Q5.MNT1 Q5.MNT2 Q8.MNT1 Q8.MNT2 U1.36 U1.37 U4.2 U4.4 U7.36 U7.37 U10.36 U10.37 U11.5 U11.6 U12.5 U12.6 U13.5 U13.6

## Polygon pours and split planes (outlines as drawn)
N187_L_OUT on Bottom Layer "N187_L_OUT_L04_P030" (solid, pour order 30): 6320,2105 6680,2105 6680,3365 6280,3365 6280,3230 6500,3230 6500,2590 6030,2590 6030,2448 6500,2448 6500,2264 6457,2221 6320,2221
N187_R_OUT on Bottom Layer (solid, pour order 43): 2490,6764 5804,6764 6230,7190 6240,7180 6790,7180 6790,7618 6523,7885 6523,8250 6777,8250 6777,9620 6320,9620 6320,9470 6523,9470 6523,8755 6040,8755 6040,8614 6510,8614 6510,8413 6178,8413 6178,8370 6176,8370 6176,7944 6550,7570 6550,7325 5905,7325 5560,6980 2490,6980
N187_L_OUT on Bottom Layer "N187_L_OUT_L04_P016" (solid, pour order 16): 6682.5,2210 6315,2210 6315,1933 6507.5,1933 6507.5,1455 6060,1455 5795,1190 2455,1190 2455,940 5880,940 6255,1315 6682.5,1315
NetD2_1 on Bottom Layer "NETD2_1_L04_P015" (solid, pour order 15): 4500,2425 4300,2425 4300,2300 3125,2300 3125,3560 2875,3560 2875,3725 4230,3725 4230,2600 4500,2600
NetD1_1 on Bottom Layer "NETD1_1_L04_P003" (solid, pour order 3): 4480,8130 3090,8130 3090,9450 2830,9450 2830,9590 4210,9590 4210,8300 4480,8300
NetJ1_A on Top Layer "NETJ1_A_L01_P001" (solid, pour order 1): 6515,7365 5470,7365 5470,8110 5890,8110 6240,7760 6240,7520 6515,7520
P187_L_OUT on Top Layer "P187_L_OUT_L01_P022" (solid, pour order 22): 5115,4925 5175,4865 5175,4285.23 5353.12,4107.12 5746.45,4109.55 6296,3560 6490,3560 6490,3405 6250,3405 6250,2775 6470,2775 6470,2630 6030,2630 6030,3492 5652,3870 5280,3870 5039,4111 5039,5085 5115,5085
NetFB2_2 on Top Layer "NETFB2_2_L01_P038" (solid, pour order 38): 6522,11974 6974,11974 6974,11452 6522,11452
NetFB1_2 on Top Layer "NETFB1_2_L01_P025" (solid, pour order 25): 6509,530 6972,530 6972,18 6509,18
P187_R_OUT on Top Layer "P187_R_OUT_L01_P029" (solid, pour order 29): 5168,10254 5231.7,10190.3 5835.72,10188.44 6211.74,9812.42 6490,9812.42 6490,9660 6281.74,9660 6281.74,8940 6490,8940 6490,8795 6061.74,8795 6061.74,9622.42 5751.74,9932.42 5094,9932.42 5094,10404 5168,10404
NetJ17_1 on Top Layer "NETJ17_1_L01_P037" (solid, pour order 37): 4994,10254 4930,10190 3810,10190 3670,10050 3670,9830 3790,9710 4160,9710 4380,9930 5068,9930 5068,10404 4994,10404
NetR67_2 on Top Layer "NONET_L06_P-001" (solid, pour order 42): 2682.83,7444.25 2922.83,7444.25 2922.83,7274.25 2682.83,7274.25
NetR71_2 on Top Layer "NONET_L06_P-001" (solid, pour order 41): 2686.97,7638.41 2926.97,7638.41 2926.97,7468.41 2686.97,7468.41
NetR68_2 on Top Layer "NONET_L06_P-001" (solid, pour order 40): 2700,1610 2940,1610 2940,1450 2700,1450
NetR73_2 on Top Layer "NONET_L06_P-001" (solid, pour order 39): 2700,1800 2940,1800 2940,1630 2700,1630
NetC35_2 on Top Layer "NETC35_2_L01_P019" (solid, pour order 19): 2500,1800 2650,1800 2650,1400 2940,1400 2940,1340 3050,1340 3050,1190 2500,1190
NetJ20_1 on Top Layer "NETJ20_1_L01_P020" (solid, pour order 20): 4935,4925 4875.22,4865 4874.75,4300.76 4697.08,4123.1 4436.9,4123.1 4210,4350 3810,4350 3700,4240 3700,3970 3800,3870 4771,3870 5012,4111 5012,5085 4935,5085
NetC5_1 on Top Layer "NETC5_1_L01_P036" (solid, pour order 36): 3480,7490 3480,7340 3540,7280 4780,7280 4780,8100 5300,8100 5300,7030 3120,7030 3120,7240 2990,7240 2990,7710 3120,7840 3120,7880 3220,7980 3560,7980 3660,7880 3660,7670
NetC34_2 on Top Layer "NETC34_2_L01_P035" (solid, pour order 35): 2490,7640 2620,7640 2620,7180 3050,7180 3050,7030 2490,7030
NetC6_1 on Top Layer "NETC6_1_L01_P018" (solid, pour order 18): 5307.33,2033.74 5307.33,1193.74 5297.33,1183.74 3107.33,1183.74 3107.33,1380 2989.05,1380 2991.01,1771.01 3098.56,1878.56 3098.56,2028.56 3220,2150 3541.07,2150 3640,2051.07 3640,1820 3468.11,1648.11 3477.33,1463.74 3527.33,1413.74 4727.33,1413.74 4727.33,2033.74
CHASIS2 on Top Layer "CHASIS2_L01_P028" (solid, pour order 28): 6874,11440.72 6614,11440.72 6614,11170.72 6874,11170.72
CHASIS1 on Top Layer "CHASIS1_L01_P026" (solid, pour order 26): 6620,530 6880,530 6880,800 6620,800
NetJ2_A on Top Layer "NETJ2_A_L01_P000" (solid, pour order 0): 6500,1495 5440,1495 5440,2060 5920,2060 6220,1760 6220,1640 6500,1640
no net on Top Overlay "NONET_L-01_P-001" (solid): 810,8130 810,8270 1520,8270 1520,8130
CHASIS2 on PWR (split plane): 6979.9,5660.09 5725.09,5660.09 5725.09,6290 5724.74,6292.61 5723.73,6295.04 5722.13,6297.13 5720.04,6298.74 5717.61,6299.74 5715,6300.09 4335,6300.09 4332.39,6299.74 4329.96,6298.74 4327.87,6297.13 4326.27,6295.04 4325.26,6292.61 4324.91,6290 4324.91,5900.09 2245.09,5900.09 2245.09,6125 2245.09,6750 2245.09,10465 2245.09,11314.91 4679.91,11314.91 4679.91,10470 4680.26,10467.39 4681.27,10464.96 4682.87,10462.87 4684.96,10461.26 4687.39,10460.26 4690,10459.91 6300,10459.91 6302.61,10460.26 6305.04,10461.26 6307.13,10462.87 6492.13,10647.87 6493.73,10649.96 6494.74,10652.39 6495.09,10655 6495.09,11979.9 6979.9,11979.9
SYS_24V on PWR (split plane): 1344.9,11515.1 1240,11515.1 1238.05,11514.71 1236.4,11513.6 1235.29,11511.95 1234.9,11510 1234.9,10345.1 885.1,10345.1 885.1,10900 884.71,10901.95 883.6,10903.6 805.1,10982.11 805.1,11814.9 1344.9,11814.9
CHASIS1 on PWR (split plane): 6979.9,20.1 6494.17,20.1 6490.09,24.18 6490.09,340 6489.74,342.61 6489.03,344.33 6488.73,345.04 6487.13,347.13 5957.13,877.13 5955.04,878.74 5952.61,879.74 5950,880.09 2260.09,880.09 2260.09,4114.43 2755,4114.43 2757.61,4114.77 2760.04,4115.78 2762.13,4117.38 2763.74,4119.47 2764.74,4121.9 2765.09,4124.51 2765.09,4320 2764.74,4322.61 2763.74,4325.04 2762.13,4327.13 2760.04,4328.73 2757.61,4329.74 2755,4330.09 2260.09,4330.09 2260.09,5434.91 4329.91,5434.91 4329.91,5135 4330.26,5132.39 4331.27,5129.96 4332.87,5127.87 4334.96,5126.27 4337.39,5125.26 4340,5124.91 5715,5124.91 5717.61,5125.26 5720.04,5126.27 5722.13,5127.87 5723.73,5129.96 5724.74,5132.39 5725.09,5135 5725.09,5639.91 6979.9,5639.91
SYS_15V on PWR (split plane): 1884.9,4785 1884.9,4435.1 155.1,4435.1 155.1,4594.9 1350,4594.9 1351.95,4595.29 1353.6,4596.4 1354.71,4598.05 1355.1,4600 1355.1,4690 1355.1,11380 1355.1,11404.9 1884.9,11404.9
SYS_5V on PWR (split plane): 6474.91,10659.18 6295.82,10480.09 4700.09,10480.09 4700.09,11325 4699.74,11327.61 4698.73,11330.04 4697.13,11332.13 4695.04,11333.74 4692.61,11334.74 4690,11335.09 2235,11335.09 2232.39,11334.74 2229.96,11333.74 2227.87,11332.13 2226.26,11330.04 2225.26,11327.61 2224.91,11325 2224.91,10465 2224.91,6750 2224.91,6125 2224.91,5890 2225.26,5887.39 2226.26,5884.96 2227.87,5882.87 2229.96,5881.27 2232.39,5880.26 2235,5879.91 4335,5879.91 4337.61,5880.26 4340.04,5881.27 4342.13,5882.87 4343.73,5884.96 4344.74,5887.39 4345.09,5890 4345.09,6279.91 5704.91,6279.91 5704.91,5650 5704.91,5145.09 4350.09,5145.09 4350.09,5445 4349.74,5447.61 4348.73,5450.04 4347.13,5452.13 4345.04,5453.73 4342.61,5454.74 4340,5455.09 2250,5455.09 2247.39,5454.74 2244.96,5453.73 2242.87,5452.13 2241.26,5450.04 2240.26,5447.61 2239.91,5445 2239.91,4320 2240.26,4317.39 2241.26,4314.96 2242.87,4312.87 2244.96,4311.27 2247.39,4310.26 2250,4309.91 2744.91,4309.91 2744.91,4134.6 2250,4134.6 2247.39,4134.26 2244.96,4133.25 2242.87,4131.64 2241.26,4129.56 2240.26,4127.12 2239.91,4124.51 2239.91,870 2240.26,867.39 2241.27,864.96 2242.87,862.87 2244.96,861.26 2247.39,860.26 2250,859.91 5945.82,859.91 6469.91,335.82 6469.91,20.1 20.1,20.1 20.1,11979.9 6474.91,11979.9
CHASIS2 on GND (split plane): 6979.9,5665.09 5725.11,5665.09 5725.11,5890 5725.11,6290 5724.77,6292.61 5723.76,6295.04 5722.15,6297.13 5720.07,6298.74 5717.63,6299.74 5715.02,6300.09 4335,6300.09 4332.39,6299.74 4329.96,6298.74 4327.87,6297.13 4326.27,6295.04 4325.26,6292.61 4324.91,6290 4324.91,5900.09 2245.09,5900.09 2245.09,10210 2245.09,10470 2245.09,11314.91 4678.66,11314.91 4678.66,10470 4679.01,10467.39 4680.02,10464.96 4681.62,10462.87 4683.71,10461.26 4686.14,10460.26 4688.75,10459.91 6300,10459.91 6302.61,10460.26 6305.04,10461.26 6307.13,10462.87 6492.13,10647.87 6493.73,10649.96 6494.74,10652.39 6495.09,10655 6495.09,11979.9 6979.9,11979.9
CHASIS1 on GND (split plane): 6979.9,20.1 6490.09,20.1 6490.09,340 6489.74,342.61 6489.03,344.33 6488.73,345.04 6487.13,347.13 5957.13,877.13 5955.04,878.74 5952.61,879.74 5950,880.09 2260.09,880.09 2260.09,3700 2260.09,4112.41 2755,4112.41 2757.61,4112.75 2760.04,4113.76 2762.13,4115.37 2763.74,4117.45 2764.74,4119.89 2765.09,4122.5 2765.09,4320.82 2764.74,4323.43 2763.74,4325.86 2762.13,4327.95 2760.04,4329.55 2757.61,4330.56 2755,4330.9 2260.09,4330.9 2260.09,4515 2260.09,5434.91 4331.85,5434.91 4331.85,5130 4332.2,5127.39 4333.2,5124.96 4334.81,5122.87 4336.9,5121.27 4339.33,5120.26 4341.94,5119.91 5714.57,5119.91 5717.18,5120.26 5719.62,5121.27 5721.7,5122.87 5723.31,5124.96 5724.32,5127.39 5724.66,5130 5724.66,5445 5724.66,5644.91 6979.9,5644.91
GND on GND (split plane): 6474.91,10659.18 6295.82,10480.09 4698.84,10480.09 4698.84,11325 4698.49,11327.61 4697.48,11330.04 4695.88,11332.13 4693.79,11333.74 4691.36,11334.74 4688.75,11335.09 2235,11335.09 2232.39,11334.74 2229.96,11333.74 2227.87,11332.13 2226.26,11330.04 2225.26,11327.61 2224.91,11325 2224.91,10470 2224.91,10210 2224.91,5890 2225.26,5887.39 2226.27,5884.96 2227.87,5882.87 2229.96,5881.27 2232.39,5880.26 2235,5879.91 4335,5879.91 4337.61,5880.26 4340.04,5881.27 4342.13,5882.87 4343.73,5884.96 4344.74,5887.39 4345.09,5890 4345.09,6279.91 5704.94,6279.91 5704.94,5890 5704.94,5657.87 5704.83,5657.61 5704.49,5655 5704.49,5445 5704.49,5140.09 4352.03,5140.09 4352.03,5445 4351.68,5447.61 4350.67,5450.04 4349.07,5452.13 4346.98,5453.73 4344.55,5454.74 4341.94,5455.09 2250,5455.09 2247.39,5454.74 2244.96,5453.73 2242.87,5452.13 2241.26,5450.04 2240.26,5447.61 2239.91,5445 2239.91,4515 2239.91,4320.82 2240.26,4318.21 2241.26,4315.77 2242.87,4313.68 2244.96,4312.08 2247.39,4311.07 2250,4310.73 2744.91,4310.73 2744.91,4132.58 2250,4132.58 2247.39,4132.24 2244.96,4131.23 2242.87,4129.63 2241.26,4127.54 2240.26,4125.11 2239.91,4122.5 2239.91,3700 2239.91,870 2240.26,867.39 2241.27,864.96 2242.87,862.87 2244.96,861.26 2247.39,860.26 2250,859.91 5945.82,859.91 6469.91,335.82 6469.91,20.1 20.1,20.1 20.1,11979.9 6474.91,11979.9

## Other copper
GND (plane layer: these items are gaps in the copper):
  lines w20: 2275,4122.5 2250,4122.5 ; 2275,4320.82 2250,4320.82 ; 5924.57,5655 6995,5655 6785,5655 5714.57,5655 ; 7000,4120 7000,0 6480,0 6480,340 5950,870 2250,870 2250,3700 2250,4122.5 ; 7000,7174.98 7000,11500 7000,11995 6485,11995 6485,10655 6300,10470 4688.75,10470 4688.75,11325 4040,11325 2235,11325 2235,10470 2235,10210 2235,5890 4335,5890 4335,6290 5715.02,6290 5715.02,5890 5715.02,5655 5714.57,5655 ; 2250,4122.5 2755,4122.5 2755,4320.82 2250,4320.82 ; 2250,4320.82 2250,4515 2250,5445 4341.94,5445 4341.94,5130 5714.57,5130 5714.57,5445 5714.57,5655
PWR (plane layer: these items are gaps in the copper):
  lines w10: 1350,11395 1350,11410 ; 1350,11410 1520,11410 1555.62,11410 1626.88,11410 1662.5,11410 1947.5,11410 1890,11410 1890,4785 1890,4430 150,4430 150,4600 1350,4600 1350,4690 1350,11380 1350,11410 ; 800,10980 800,11820 1350,11820 1350,11510 1240,11510 1240,10340 880,10340 880,10900 800,10980
  lines w20: 5715,5650 5715,5135 4340,5135 4340,5445 3800,5445 2250,5445 2250,4320 2275,4320 2755,4320 2755,4124.51 2250,4124.51 2250,870 5950,870 6480,340 6480,20 6490,10 7000,10 7000,3890 7000,5650 ; 5715,5650 5715,6290 5620,6290 4335,6290 4335,5890 4245,5890 2235,5890 2235,6125 2235,6750 2235,10465 2235,11325 3830,11325 4690,11325 4690,10470 6300,10470 6485,10655 6485,12000 7000,12000 7000,5650 ; 5715,5650 7000,5650 ; 5715,5650 7000,5650

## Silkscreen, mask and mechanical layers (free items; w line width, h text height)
Top Overlay:
  text "34" at 2366,11776 h40
  text "GND" at 4890,11681.31 h50 r45
  text "64" at 746,11676 h40
  text "2" at 4086,11676 h40
  text "CHASSIS" at 6506,11601 h40 r90
  text "63" at 745,11592 h40
  text "1" at 4096,11576 h40
  text "33" at 2366,11486 h40
  text "24V" at 910,11401.31 h50 r45
  text "WARNING!" at 5088.4,11237.26 h150
  text "HIGH VOLTAGE!" at 5088.4,10962.26 h150
  text "WARNING!" at 5087.25,10681.33 h150
  text "15V" at 1650,10291.31 h50 r45
  text "P187_R" at 4364.11,9827.2 h50 r45
  text "HPB R" at 6940,9510 h60 r90
  text "HPB R" at 6230,9500 h60 r90
  text "IPB A" at 6220,8850 h60 r90
  text "INPUT GROUND FAULT BOARD" at 640,8670 h60
  text "IPB A" at 6950,8630 h60 r90
  text "N187_R" at 5924.11,8627.2 h50 r45
  text "7/25/2023   V1.0" at 640,8550 h60
  text "WARNING HIGH VOLTAGE!" at 5710,8510 h80 r90
  text "375V RIGHT PROTECTION" at 5510,8500 h80 r90
  text "APL MARS" at 638.54,8424.6 h60
  text "K. ZACK" at 640,8310 h60
  text "SN:" at 633.19,8182.59 h60
  text "P187_R_IN" at 5954.11,7527.2 h50 r45
  text "MVC IN R" at 6250,7100 h60 r90
  text "MVC IN R" at 6950,7090 h60 r90
  text "GND" at 330,7061.31 h50 r45
  text "N187_R_IN" at 5604.11,6917.2 h50 r45
  text "5V" at 340,6711.31 h50 r45
  text "CURRENT LIMIT" at 6298,5993 h40
  text "SET RESISTOR" at 6318,5873 h40
  text "GF_H" at 6794.11,5737.2 h50 r45
  text "GF_L" at 6254.11,5662.2 h50 r45
  text "GF_SIG" at 414.11,5097.2 h50 r45
  text "ANNODE" at 6240,5080 h60 r90
  text "ANNODE" at 6950,5070 h60 r90
  text "P187_L" at 4244.11,4157.2 h50 r45
  text "IPB B" at 6212.48,3355.22 h60 r90
  text "IPB B" at 6942.48,3355.22 h60 r90
  text "HPB L" at 6230,2700 h60 r90
  text "HPB L" at 6940,2600 h60 r90
  text "375V LEFT PROTECTION" at 5370,2440 h80 r90
  text "WARNING HIGH VOLTAGE!" at 5540,2410 h80 r90
  text "N187_L" at 6028.11,2270.2 h50 r45
  text "TEMPERATURE" at 50,2120 h60 r270
  text "TEMPERATURE" at 760,2080 h60 r270
  text "P187_L_IN" at 5904.11,1507.2 h50 r45
  text "MVC IN R" at 6942.64,1248.4 h60 r90
  text "MVC IN R" at 6230,1240 h60 r90
  text "N187_L_IN" at 5704.11,997.2 h50 r45
  text "34" at 2366,476 h40
  text "GND" at 4800,401.31 h50 r45
  text "64" at 746,376 h40
  text "2" at 4096,376 h40
  text "63" at 746,276 h40
  text "1" at 4106,276 h40
  text "CHASSIS" at 6477,198 h40 r90
  text "33" at 2366,186 h40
